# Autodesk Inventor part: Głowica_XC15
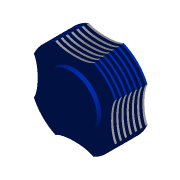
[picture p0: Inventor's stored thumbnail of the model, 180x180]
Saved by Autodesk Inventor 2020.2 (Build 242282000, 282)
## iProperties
Created: 2000-11
Part Number: Głowica_XC15
Material: Aluminum
Document SubType Name: Modeling
Designer: F.Stasiak
Stock Number: Głowica_XC15
Density: 2.71 g/cm^3
Appearance: Niebieski (matowy)
Manager: www.cadconsulting.pl
Company: Fabian Stasiak CAD Consulting
Control State: 0
Master: False
Checked Out: False
Shininess: 5.0
Density: 2.71
Volumn: 397.86405690972106
Area: 1617.8979658065996
PropertySet Name: Model Information
Author: F.Stasiak
Subject: Zbiór ćwiczeń. Autodesk Inventor 2020. Kurs podstawowy
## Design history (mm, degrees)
node "Extrusion1" dims "d1" = 118, "d2" = 0
  sketch "Sketch1"
    geometry: C1 r 85 at (0, 0); 1 further point
    constraints: 1 centre point, 1 coincident
    dimensions: "d0" = 170 diameter of C1
feature "Szkic powierzchni1" dims angle "d27" = 2.5 deg
node "Płaszczyzna konstrukcyjna1"
sketch "Szkic5"
  geometry: C1 r 135 at (0, 0); C2 r 75 at (0, 0); 1 further point
  constraints: 2 centre point, 2 coincident
  dimensions: "d29" = 270 diameter of C1; "d30" = 60 radial gap between concentric circles of C1 C2
extrude "Wyciągnięcie proste4" join sketch "Szkic5" stored distance "d31" = 6; taper "d32" = 0 deg
pattern_linear "Szyk prostokątny1" dims "d35" = 15
sketch "Szkic6"
  geometry: L1 (0, 0)-(0, 135); 1 further point; 1 other entity
  constraints: 2 end point, 2 vertical, 1 coincident, 1 vertical alignment, 3 other
extrude "Wyciągnięcie proste5" cut sketch "Szkic6" extent not by distance; stored distance "d36" = 6; taper "d37" = 2.5 deg
pattern_circular "Szyk kołowy3" dims angle "d39" = 360 deg
sketch "Szkic7"
  geometry: C1 r 85 at (0, 0) reference; C2 r 70 at (0, 0)
  constraints: 1 centre point, 1 coincident
  dimensions: "d43" = 140 diameter of C2
extrude "Wyciągnięcie proste6" cut sketch "Szkic7" distance "d41" = 100; taper "d42" = -2.5 deg
node "Bryła1"
node "Korpusy bryłowe"
node "Korpusy powierzchniowe"
other parameters: "d28" = -15
